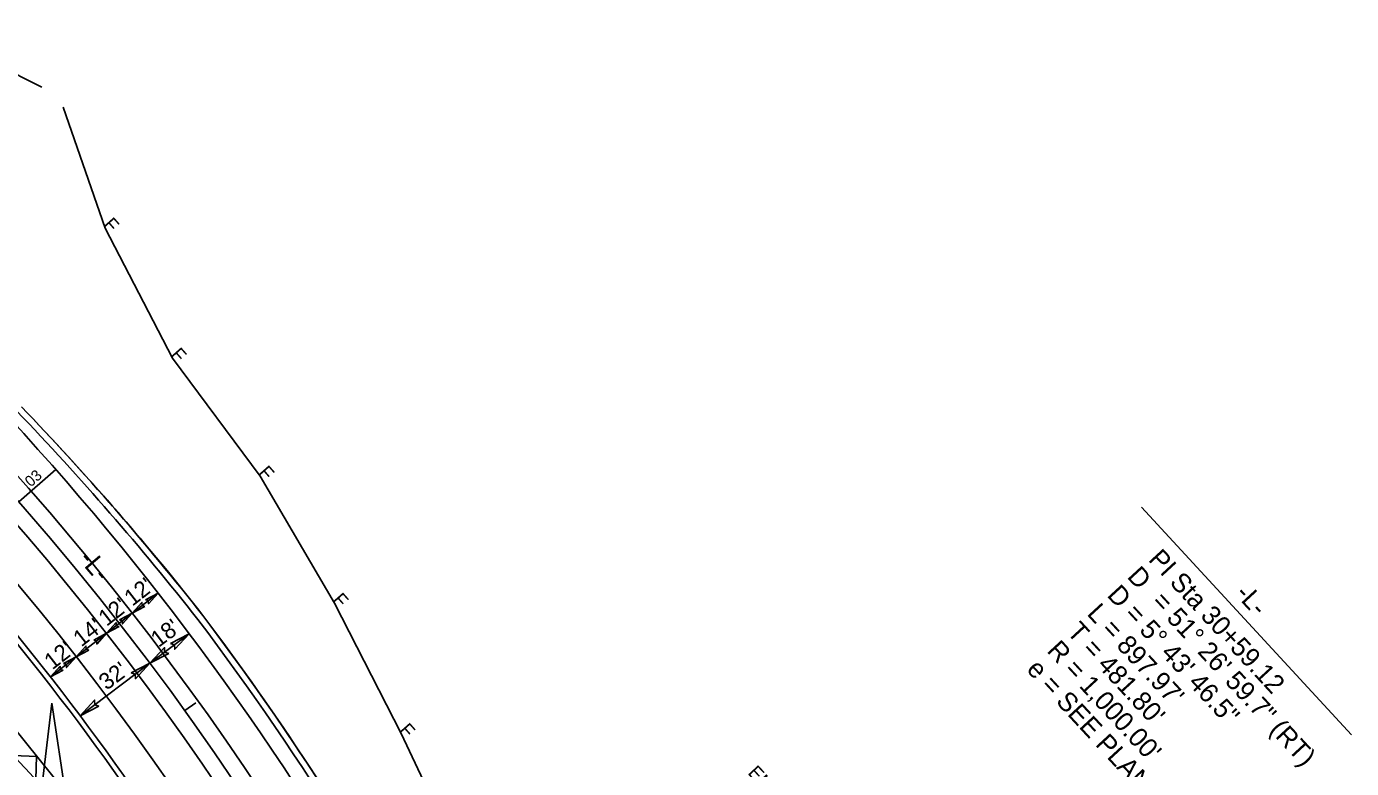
# Model space of a CAD drawing. Extents: x 1702862 to 1704514, y 793768 to 796215.
# Drawn here: x 1703743.4 to 1704228.7, y 794686.7 to 794958.5 of the extents above; entities that cross this region are included whole.
import ezdxf

# ---------------------------------------------------------------- set-up
doc = ezdxf.new("R2010")
doc.units = 0
for name, color, linetype in [('Default', 7, 'Continuous'), ('Prop Conc 2ft 6in Curb and Gutter', 7, 'Continuous'), ('Prop Conc Shoulder Berm Gutter', 7, 'Continuous'), ('Prop Dimension', 7, 'Continuous'), ('Prop Dimension Text', 7, 'Continuous'), ('Prop EOT', 7, 'Continuous'), ('Prop Guardrail', 7, 'Continuous'), ('Prop Horizontal Alignment', 7, 'Continuous'), ('Prop Horizontal Alignment Curve and Spiral Data', 7, 'Continuous'), ('Prop Horizontal Alignment Direction Label', 7, 'Continuous'), ('Prop Horizontal Alignment Tick Small', 7, 'Continuous'), ('Prop Lane Lines', 7, 'Continuous'), ('Prop Paved Shoulder', 7, 'Continuous'), ('Prop Rem of Exist Asph Pvmt', 7, 'Continuous'), ('Prop SS Fill Line', 7, 'Continuous'), ('Prop SS Misc', 7, 'Continuous'), ('Prop Superelevation  Arrow CELL', 7, 'Continuous'), ('Prop Superelevation Label', 7, 'Continuous'), ('Prop Terminator CELL', 7, 'Continuous')]:
    doc.layers.add(name, color=color, linetype=linetype)

msp = doc.modelspace()

# ---------------------------------------------------------------- linework, layer by layer
at = {"layer": 'Prop Conc 2ft 6in Curb and Gutter'}
msp.add_arc((1702985.28, 794122.36), 970.46, 32.25438, 42.65517, dxfattribs=at)
at = {"layer": 'Prop Conc Shoulder Berm Gutter'}
for centre, radius, start, end in [((1703001.93, 794109.28), 1025.22, 38.16066, 43.82598), ((1702988.97, 794124.56), 1026.16, 26.22656, 37.0429)]:
    msp.add_arc(centre, radius, start, end, dxfattribs=at)
at = {"layer": 'Prop Dimension'}
for p, q in [((1703791.62, 794750.99), (1703782.16, 794743.61)), ((1703782.16, 794743.61), (1703772.7, 794736.22)), ((1703772.7, 794736.22), (1703761.66, 794727.61)), ((1703803.04, 794736.07), (1703788.65, 794725.26)), ((1703761.66, 794727.61), (1703752.2, 794720.23)), ((1703788.65, 794725.26), (1703763.06, 794706.04)), ((1703752.73, 794710.66), (1703728.81, 794512.1)), ((1703752.73, 794710.66), (1703782.26, 794512.85))]:
    msp.add_line(p, q, dxfattribs=at)
at = {"layer": 'Prop EOT'}
for radius, start, end in [(1018, 14.75888, 42.70907), (968, 32.4282, 42.70916)]:
    msp.add_arc((1702989.11, 794124.65), radius, start, end, dxfattribs=at)
at = {"layer": 'Prop Guardrail'}
for centre, radius, start, end in [((1703002.29, 794108.92), 1025.21, 38.32941, 43.85449), ((1702988.97, 794124.56), 1026.16, 25.07101, 37.18325)]:
    msp.add_arc(centre, radius, start, end, dxfattribs=at)
at = {"layer": 'Prop Horizontal Alignment'}
msp.add_arc((1702989.11, 794124.65), 1000, 351.25916, 42.70907, dxfattribs=at)
at = {"layer": 'Prop Horizontal Alignment Curve and Spiral Data'}
msp.add_line((1704151.77, 794782.38), (1704228.7, 794699.03), dxfattribs=at)
at = {"layer": 'Prop Horizontal Alignment Tick Small'}
msp.add_line((1703801.4, 794707.9), (1703805.46, 794710.81), dxfattribs=at)
at = {"layer": 'Prop Lane Lines'}
for radius, start in [(1006, 0.00687), (994, 359.40932), (980, 359.40932)]:
    msp.add_arc((1702989.11, 794124.65), radius, start, 42.70907, dxfattribs=at)
at = {"layer": 'Prop Paved Shoulder'}
for centre, radius, start, end in [((1703001.93, 794109.28), 1022.89, 38.16066, 43.82598), ((1702988.97, 794124.56), 1023.83, 26.22656, 37.0429)]:
    msp.add_arc(centre, radius, start, end, dxfattribs=at)
at = {"layer": 'Prop Rem of Exist Asph Pvmt'}
for p, q in [((1703738.66, 794691.45), (1703747.25, 794691.11)), ((1703747.15, 794691.23), (1703746.8, 794682.65))]:
    msp.add_line(p, q, dxfattribs=at)
msp.add_spline([(1703779.68, 794644.96), (1703761.75, 794665.91), (1703731.32, 794699.4), (1703700.82, 794732.47), (1703669.4, 794765.36)], degree=3, dxfattribs=at)
at = {"layer": 'Prop SS Fill Line'}
for p, q in [((1703704.77, 794958.5), (1703749.05, 794936.28)), ((1703756.85, 794928.93), (1703772.24, 794884.69)), ((1703772.24, 794884.69), (1703796.9, 794837.04)), ((1703796.9, 794837.04), (1703829.05, 794793.83)), ((1703829.05, 794793.83), (1703856.18, 794747.23)), ((1703856.18, 794747.23), (1703880.62, 794699.51)), ((1703728.84, 794713.99), (1703758.51, 794677.1)), ((1703880.62, 794699.51), (1703903.35, 794651.42))]:
    msp.add_line(p, q, dxfattribs=at)
at = {"layer": 'Prop Superelevation  Arrow CELL'}
msp.add_line((1703740.64, 794784.34), (1703754.17, 794796.22), dxfattribs=at)
at = {"layer": 'Prop Terminator CELL'}
for points in [[(1703786.99, 794748.51), (1703791.62, 794750.99), (1703788.08, 794747.06), (1703788.04, 794748.19)], [(1703786.79, 794746.09), (1703782.16, 794743.61), (1703785.69, 794747.53), (1703785.74, 794746.4)], [(1703777.53, 794741.12), (1703782.16, 794743.61), (1703778.62, 794739.68), (1703778.58, 794740.81)], [(1703768.07, 794733.74), (1703772.7, 794736.22), (1703769.16, 794732.3), (1703769.12, 794733.43)], [(1703777.33, 794738.7), (1703772.7, 794736.22), (1703776.23, 794740.15), (1703776.28, 794739.02)], [(1703796.13, 794732.53), (1703803.04, 794736.07), (1703797.7, 794730.37), (1703797.67, 794732.04)], [(1703766.29, 794730.09), (1703761.66, 794727.61), (1703765.2, 794731.54), (1703765.24, 794730.4)], [(1703757.03, 794725.13), (1703761.66, 794727.61), (1703758.13, 794723.68), (1703758.08, 794724.81)], [(1703795.55, 794728.81), (1703788.65, 794725.26), (1703793.98, 794730.97), (1703794.02, 794729.3)], [(1703756.83, 794722.71), (1703752.2, 794720.23), (1703755.74, 794724.15), (1703755.78, 794723.02)], [(1703781.74, 794721.72), (1703788.65, 794725.26), (1703783.31, 794719.56), (1703783.28, 794721.23)], [(1703769.97, 794709.59), (1703763.06, 794706.04), (1703768.39, 794711.75), (1703768.43, 794710.08)]]:
    msp.add_lwpolyline(points, close=True, dxfattribs=at)

# ---------------------------------------------------------------- texts
at = {"layer": 'Default'}
msp.add_text('END SBG', height=5, rotation=312.7091, dxfattribs=at).set_placement((1704007.35, 794684.94))
at = {"layer": 'Prop Dimension Text'}
for s, rotation, p in [("12'", 37.9714, (1703782.19, 794745.92)), ("12'", 37.9714, (1703772.75, 794738.55)), ("14'", 37.9714, (1703763.5, 794731.04)), ("18'", 36.9141, (1703791.81, 794730.85)), ("12'", 37.9714, (1703752.9, 794722.64)), ("32'", 36.9141, (1703772.77, 794715.15))]:
    msp.add_text(s, height=6, rotation=rotation, dxfattribs=at).set_placement(p)
at = {"layer": 'Prop Horizontal Alignment Curve and Spiral Data'}
for s, p in [('PI Sta 30+59.12', (1704154.01, 794763.05)), ('D', (1704146.21, 794756.76)), ('D = 5%%d 43\' 46.5"', (1704138.86, 794749.98)), ('= 51%%d 26\' 59.7" (RT)', (1704155.14, 794747.52)), ('-L-', (1704185.8, 794750.44)), ("L = 897.97'", (1704131.51, 794743.2)), ("T = 481.80'", (1704124.16, 794736.42)), ("R = 1,000.00'", (1704116.82, 794729.63)), ('e = SEE PLANS', (1704109.37, 794722.73))]:
    msp.add_text(s, height=7, rotation=312.7091, dxfattribs=at).set_placement(p)
at = {"layer": 'Prop Horizontal Alignment Direction Label'}
msp.add_text('-L-', height=7, rotation=310.3963, dxfattribs=at).set_placement((1703762.24, 794763.25))
at = {"layer": 'Prop SS Misc'}
for p in [(1703771.3, 794885.76), (1703795.96, 794838.1), (1703828.11, 794794.89), (1703855.24, 794748.29), (1703879.68, 794700.57)]:
    msp.add_text('F', height=5, rotation=311.4091, dxfattribs=at).set_placement(p)
at = {"layer": 'Prop Superelevation Label'}
msp.add_text('03', height=4, rotation=41.2768, dxfattribs=at).set_placement((1703744.98, 794789.6))

doc.saveas('drawing.dxf')
